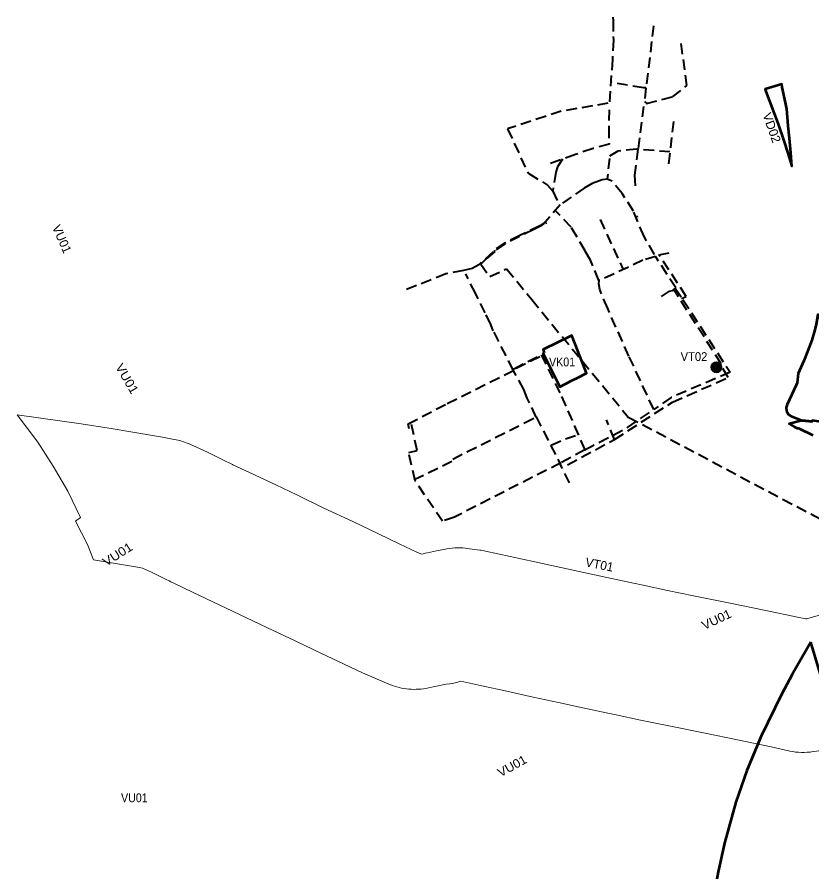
# Model space of a CAD drawing. Extents: x -650145 to -642675, y -1074338 to -1066803.
# Drawn here: x -649600 to -647799, y -1068740 to -1066803 of the extents above; entities that cross this region are included whole.
import ezdxf

# ---------------------------------------------------------------- set-up
doc = ezdxf.new("R2010")
doc.units = 0
doc.header["$LTSCALE"] = 8
doc.linetypes.add('MEDIUM_DASHED', pattern=[4.5, 3, -1.5])
for name, color, linetype in [('1', 7, 'Continuous'), ('17', 7, 'Continuous'), ('2', 7, 'Continuous'), ('8', 7, 'Continuous')]:
    doc.layers.add(name, color=color, linetype=linetype)
for name, color, linetype, lineweight in [('12', 7, 'MEDIUM_DASHED', 40), ('13', 7, 'MEDIUM_DASHED', 40), ('15', 7, 'Continuous', 13), ('44', 7, 'Continuous', 53), ('45', 7, 'Continuous', 53), ('53', 7, 'Continuous', 53)]:
    doc.layers.add(name, color=color, linetype=linetype, lineweight=lineweight)

msp = doc.modelspace()

# ---------------------------------------------------------------- hatches: boundary and pattern name
at = {"layer": '15'}
msp.add_hatch(color=256, dxfattribs=at).paths.add_polyline_path([(-648003.776, -1067596.576, 1), (-648027.301, -1067596.576, 1)])

# ---------------------------------------------------------------- linework, layer by layer
at = {"layer": '12'}
for p, q in [((-648180.97, -1066963.362), (-648253.957, -1066951.838)), ((-648278.693, -1067262.163), (-648226.9, -1067375.166)), ((-648196.766, -1067253.967), (-648195.142, -1067257.678)), ((-648004.854, -1067588.588), (-648113.009, -1067418.699)), ((-648415.786, -1067572.959), (-648475.864, -1067602.844)), ((-648423.943, -1067708.847), (-648369.189, -1067816.082)), ((-648614.737, -1067809.85), (-648698.776, -1067851.063)), ((-648348.302, -1067858.558), (-648369.189, -1067816.082))]:
    msp.add_line(p, q, dxfattribs=at)
for points in [[(-648175.148, -1066963.826), (-648180.97, -1066963.362), (-648253.957, -1066951.838)], [(-648364.124, -1067125.28), (-648375.197, -1067142.997), (-648379.372, -1067154.48), (-648386.313, -1067197.539)], [(-648443.711, -1067154.017), (-648440.351, -1067157.668), (-648398.143, -1067183.811), (-648386.313, -1067197.539), (-648370.813, -1067230.283)], [(-648369.562, -1067228.854), (-648409.651, -1067274.641), (-648429.367, -1067284.499), (-648494.475, -1067317.053), (-648521.596, -1067335.324), (-648554.018, -1067364.678), (-648568.696, -1067372.565), (-648588.85, -1067377.165), (-648628.502, -1067385.052), (-648726.865, -1067424.267)], [(-648094.889, -1067440.922), (-648083.603, -1067436.086), (-648142.993, -1067345.999), (-648145.677, -1067341.766), (-648113.431, -1067335.317)], [(-648423.528, -1067709.42), (-648443.952, -1067666.645), (-648451.709, -1067646.623), (-648475.864, -1067602.844), (-648520.943, -1067513.857), (-648526.757, -1067499.387), (-648539.522, -1067473.638), (-648561.687, -1067428.819), (-648583.575, -1067384.979)], [(-648109.211, -1067417.4), (-648091.36, -1067443.354), (-647984.432, -1067607.856), (-648117.975, -1067665.279), (-648157.356, -1067692.42), (-648213.545, -1067571.236), (-648261.841, -1067463.452), (-648279.42, -1067420.616), (-648282.213, -1067407.759), (-648280.834, -1067400.369)], [(-648474.791, -1067599.992), (-648412.884, -1067568.459), (-648366.45, -1067662.56), (-648313.561, -1067783.49), (-648368.053, -1067813.183), (-648608.847, -1067935.845), (-648636.198, -1067945.076), (-648698.161, -1067853.768), (-648712.726, -1067789.669)], [(-648246.445, -1067760.157), (-648115.043, -1067675.511), (-647988.478, -1067619.887), (-647988.478, -1067619.887), (-648005.649, -1067590.208)], [(-648711.295, -1067736.072), (-648714.211, -1067724.896), (-648625.432, -1067678.873), (-648472.986, -1067602.783)], [(-648313.561, -1067783.49), (-648216.797, -1067733.386), (-648157.356, -1067692.42)], [(-648612.856, -1067804.638), (-648450.653, -1067722.822), (-648422.77, -1067708.995)], [(-648352.857, -1067817.393), (-648246.445, -1067760.157), (-648264.647, -1067715.995)], [(-648712.726, -1067789.669), (-648693.5, -1067785.007), (-648707.44, -1067722.32)], [(-648389.839, -1067773.142), (-648357.354, -1067758.497), (-648333.234, -1067750.865)]]:
    msp.add_lwpolyline(points, dxfattribs=at)
at = {"layer": '13'}
for p, q in [((-648112.923, -1067040.185), (-648124.357, -1067140.948)), ((-648182.009, -1067354.313), (-648280.834, -1067400.369))]:
    msp.add_line(p, q, dxfattribs=at)
for points in [[(-648249.873, -1066803.466), (-648249.73, -1066811.744), (-648248.971, -1066855.783), (-648251.033, -1066899.78), (-648258.055, -1066998.612)], [(-648157.752, -1066823.288), (-648175.148, -1066963.826), (-648178.059, -1066994.515), (-648172.511, -1066999.942)], [(-648173.728, -1066999.249), (-648115.19, -1066984.032), (-648082.101, -1066958.613), (-648096.04, -1066857.23)], [(-648261.097, -1066998.621), (-648367.277, -1067016.878), (-648488.5, -1067056.457), (-648443.711, -1067154.017)], [(-648258.415, -1067013.596), (-648259.37, -1067053.379), (-648258.664, -1067091.005)], [(-648180.44, -1067005.928), (-648193.182, -1067102.911), (-648200.826, -1067161.68), (-648199.291, -1067196.561)], [(-648258.664, -1067091.005), (-648295.035, -1067101.44), (-648334.906, -1067114.73), (-648398.945, -1067137.853)], [(-648120.689, -1067108.619), (-648196.172, -1067102.839), (-648238.811, -1067107.157), (-648257.45, -1067118.693)], [(-648258.055, -1067123.482), (-648262.874, -1067170.801), (-648274.266, -1067172.334), (-648297.049, -1067180.221), (-648315.013, -1067191.174), (-648365.989, -1067226.386)], [(-648203.542, -1067243.239), (-648228.816, -1067203.221), (-648251.518, -1067175.177), (-648262.874, -1067170.801)], [(-648282.082, -1067399.914), (-648300.965, -1067354.129), (-648313.139, -1067332.931), (-648344.694, -1067279.025), (-648380.675, -1067241.546)], [(-648155.756, -1067341.148), (-648179.43, -1067300.686), (-648202.861, -1067243.899)], [(-648399.807, -1067271.705), (-648403.795, -1067268.335), (-648415.725, -1067276.026), (-648460.621, -1067297.861), (-648494.503, -1067315.615), (-648518.853, -1067331.303), (-648517.514, -1067334.113), (-648535.229, -1067349.36), (-648541.751, -1067355.211), (-648549.313, -1067362.847), (-648528.927, -1067391.383), (-648490.779, -1067373.709), (-648433.887, -1067443.425), (-648215.035, -1067709.37), (-647316.251, -1068186.868)], [(-648139.544, -1067436.218), (-648121.567, -1067424.473), (-648112.071, -1067422.048), (-648107.639, -1067416.402), (-648153.124, -1067346.062), (-648182.102, -1067354.113)]]:
    msp.add_lwpolyline(points, dxfattribs=at)
at = {"layer": '15'}
for points in [[(-649382.683, -1067736.41), (-649454.621, -1067724.642), (-649600.146, -1067704.069)], [(-649600.146, -1067704.069), (-649553.44, -1067766.28), (-649518.25, -1067820.92), (-649485.13, -1067877.09), (-649456.24, -1067937.25), (-649467.89, -1067945.1), (-649440.52, -1067998.08), (-649427.146, -1068033.129), (-649350.073, -1068045.91)], [(-647774.267, -1068155.557), (-647802.757, -1068163.967), (-647805.815, -1068164.87), (-647810.703, -1068166.542), (-647812.571, -1068166.788), (-647827.9, -1068163.347), (-647906.909, -1068147.095), (-647980.144, -1068131.782), (-648067.22, -1068114.186), (-648126.418, -1068101.998), (-648181.06, -1068090.497), (-648203.256, -1068085.824), (-648264.087, -1068072.869), (-648309.141, -1068062.702), (-648367.602, -1068050.464), (-648426.568, -1068037.47), (-648482.748, -1068025.289), (-648538.58, -1068012.914), (-648541.779, -1068012.205), (-648548.234, -1068011.067), (-648551.482, -1068010.64), (-648580.682, -1068006.8), (-648583.733, -1068006.399), (-648589.862, -1068005.847), (-648596.008, -1068005.548), (-648602.162, -1068005.5), (-648608.312, -1068005.705), (-648614.449, -1068006.163), (-648620.561, -1068006.871), (-648626.64, -1068007.83), (-648629.657, -1068008.433), (-648649.671, -1068012.436), (-648670.491, -1068016.914), (-648675.031, -1068017.89), (-648677.625, -1068018.618), (-648680.26, -1068018.992), (-648683.7, -1068019.718), (-648693.991, -1068015.264), (-648732.758, -1067996.958), (-648781.439, -1067974.125), (-648839.635, -1067946.226), (-648905.118, -1067915.461), (-648966.216, -1067885.853), (-649013.828, -1067863.231), (-649073.136, -1067835.331), (-649111.1, -1067817.381), (-649111.919, -1067816.904), (-649116.61, -1067814.593), (-649129.493, -1067808.246), (-649168.436, -1067789.027), (-649210.538, -1067770.325), (-649214.568, -1067768.535), (-649222.823, -1067765.435), (-649231.246, -1067762.826), (-649239.808, -1067760.715), (-649244.144, -1067759.913), (-649270.928, -1067754.958), (-649346.551, -1067742.368), (-649382.683, -1067736.41)], [(-649350.073, -1068045.91), (-649322.852, -1068050.442), (-649316.134, -1068051.685), (-649295.764, -1068060.733), (-649262.167, -1068077.314), (-649255.583, -1068080.557), (-649251.7, -1068082.747), (-649246.836, -1068085.047), (-649201.104, -1068106.669), (-649142.052, -1068134.449), (-649096.004, -1068156.327), (-649034.322, -1068186.219), (-648968.265, -1068217.254), (-648909.981, -1068245.195), (-648860.502, -1068268.402), (-648817.649, -1068288.636), (-648773.793, -1068307.617), (-648757.876, -1068314.337), (-648755.322, -1068315.416), (-648750.136, -1068317.382), (-648744.882, -1068319.156), (-648739.566, -1068320.735), (-648734.195, -1068322.115), (-648728.777, -1068323.297), (-648723.319, -1068324.277), (-648717.828, -1068325.055), (-648712.312, -1068325.63), (-648706.779, -1068326), (-648701.236, -1068326.166), (-648695.69, -1068326.126), (-648690.15, -1068325.882), (-648684.623, -1068325.433), (-648679.116, -1068324.78), (-648673.637, -1068323.924), (-648670.915, -1068323.395), (-648657.024, -1068320.696), (-648628.18, -1068314.608), (-648619.413, -1068313.366), (-648614.155, -1068312.621), (-648603.771, -1068310.391), (-648594.694, -1068307.758), (-648546.992, -1068318.331), (-648490.632, -1068330.55)], [(-648490.632, -1068330.55), (-648430.618, -1068343.776), (-648372.899, -1068355.858), (-648328.353, -1068365.911), (-648265.404, -1068379.316), (-648242.86, -1068384.063), (-648187.562, -1068395.702), (-648127.18, -1068408.134)], [(-648127.18, -1068408.134), (-648040.556, -1068425.638), (-647967.831, -1068440.845), (-647890.98, -1068456.653), (-647852.243, -1068465.348), (-647849.022, -1068466.071), (-647842.522, -1068467.232), (-647835.978, -1068468.107), (-647829.402, -1068468.692), (-647822.806, -1068468.988), (-647816.203, -1068468.993), (-647809.607, -1068468.707), (-647803.03, -1068468.132), (-647799.757, -1068467.7), (-647755.597, -1068461.87)]]:
    msp.add_lwpolyline(points, dxfattribs=at)
at = {"layer": '15', "lineweight": 35}
msp.add_circle((-648015.538, -1067596.576), 11.762, dxfattribs=at)
at = {"layer": '44'}
for points in [[(-647801.797, -1068219.34), (-647843.6, -1068292.629), (-647868.214, -1068337.803), (-647914.339, -1068432.512), (-647946.187, -1068510.254), (-647971.074, -1068581.98), (-647997.27, -1068674.747), (-648011.775, -1068739.718), (-648023.914, -1068809.332), (-648030.73, -1068861.213), (-648038.596, -1068968.281)], [(-647771.413, -1068334.626), (-647774.94, -1068311.47), (-647779.55, -1068292.23), (-647780.07, -1068290.53), (-647801.797, -1068219.34)]]:
    msp.add_lwpolyline(points, dxfattribs=at)
at = {"layer": '45'}
for points in [[(-647777.55, -1067496.95), (-647781.85, -1067479.19), (-647785.64, -1067477.02), (-647789.39, -1067498.84), (-647792.54, -1067511.85), (-647799.39, -1067535.48)], [(-647799.39, -1067535.48), (-647808.71, -1067561.03), (-647817.59, -1067582.4)], [(-647817.59, -1067582.4), (-647829.97, -1067610.62), (-647832.8, -1067631.53), (-647835.06, -1067637.01), (-647855.24, -1067681.26), (-647857.51, -1067687.74), (-647856.9, -1067695.97)], [(-647856.9, -1067695.97), (-647852.3, -1067703.36), (-647845.74, -1067707.59), (-647821.02, -1067717.33)], [(-647821.02, -1067717.33), (-647850.45, -1067724.77), (-647838.18, -1067731.62), (-647832.56, -1067734.22), (-647829.49, -1067734.58)], [(-647829.49, -1067734.58), (-647796.87, -1067750.25)], [(-647708.71, -1067723.99), (-647720.45, -1067726.49), (-647732.71, -1067727.02), (-647745.41, -1067726.6), (-647768.53, -1067722.82), (-647783.13, -1067719.68), (-647798.17, -1067717.58), (-647798.5, -1067719.67), (-647821.02, -1067717.33)], [(-647821.02, -1067717.33), (-647798.5, -1067719.67), (-647798.17, -1067717.58)]]:
    msp.add_lwpolyline(points, dxfattribs=at)
msp.add_lwpolyline([(-648405.41, -1067563.84), (-648408.002, -1067565.219), (-648369.949, -1067640.851), (-648342.697, -1067626.806), (-648328.54, -1067619.51), (-648309.522, -1067609.713), (-648317.43, -1067590), (-648343.41, -1067524.81), (-648408.26, -1067556.58)], close=True, dxfattribs=at)
at = {"layer": '53'}
msp.add_lwpolyline([(-647876.57, -1067043.5), (-647863.04, -1067081.36), (-647853.65, -1067111.91), (-647844.3, -1067141.25), (-647847.09, -1067110.58), (-647850.07, -1067077.71), (-647852.63, -1067049.52), (-647856.11, -1067011.21), (-647866.14, -1066961.98), (-647867.46, -1066955.52), (-647905.28, -1066967.07), (-647903.5, -1066972.05)], close=True, dxfattribs=at)

# ---------------------------------------------------------------- texts
at = {"layer": '1', "width": 0.9}
msp.add_text('VK01', height=20, dxfattribs=at).set_placement((-648394.54, -1067594.58))
at = {"layer": '17', "width": 0.95}
msp.add_text('VT02', height=20, dxfattribs=at).set_placement((-648096.61, -1067582.461))
at = {"layer": '17'}
msp.add_text('VT01', height=20, rotation=348.908, dxfattribs=at).set_placement((-648313.65, -1068047.434))
at = {"layer": '2'}
msp.add_text('VU01', height=20, rotation=293.833, dxfattribs=at).set_placement((-649521.27, -1067279.43))
for rotation, width, p in [(300.389, 1.1, (-649378.291, -1067595.604)), (32.546, 1.1, (-649398.133, -1068048.567)), (25.207, 1.05, (-648042.803, -1068191.925)), (29.08, 1.05, (-648504.265, -1068525.557)), (0.068, 0.9, (-649364.51, -1068581.837))]:
    msp.add_text('VU01', height=20, rotation=rotation, dxfattribs=dict(at, width=width)).set_placement(p)
at = {"layer": '8', "width": 1.05}
msp.add_text('VD02', height=20, rotation=289.545, dxfattribs=at).set_placement((-647911.193, -1067024.391))

doc.saveas('drawing.dxf')
